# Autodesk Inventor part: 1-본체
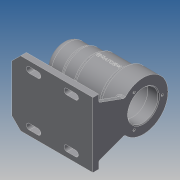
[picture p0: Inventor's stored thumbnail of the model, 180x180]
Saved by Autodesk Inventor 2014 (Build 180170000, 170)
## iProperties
Created: 2017-09
Part Number: 1-본체
Material: Generic
Document SubType Name: Modeling
Designer: kb542-00
Density: 1 g/cm^3
Appearance: Default
Author: kb542-00
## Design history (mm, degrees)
sketch "스케치1"
  geometry: L1 (-112, 0)-(0, 0); L2 (0, 21)-(0, 34); L3 (0, 34)-(-28, 34); L4 (-28, 34)-(-28, 30); L5 (-28, 30)-(-67, 30); L6 (-67, 30)-(-67, 27); L7 (-67, 27)-(-87, 27); L8 (-87, 27)-(-87, 25); L9 (-87, 25)-(-112, 25); L10 (-112, 25)-(-112, 0); L11 (-106, 0)-(-106, 10.5); L12 (-106, 10.5)-(-103, 10.5); L13 (-103, 10.5)-(-103, 16); L14 (-103, 16)-(-99, 16); L15 (-99, 16)-(-99, 17.5); L16 (-99, 17.5)-(-81, 17.5); L17 (-81, 17.5)-(-81, 21); L18 (-81, 21)-(-69, 21); L19 (-69, 21)-(-69, 24); L20 (-69, 24)-(-15, 24); L21 (-15, 24)-(-15, 21); L22 (-15, 21)-(0, 21); 1 further point
  constraints: 44 end point, 15 parallel, 6 perpendicular, 1 coincident, 1 horizontal, 1 point on line, 1 vertical alignment
  dimensions: "d0" = 68 diameter of L3 L1; "d1" = 42 diameter of L22 L1; "d2" = 112 distance between parallel lines of L2 L10; "d3" = 25 distance between parallel lines of L8 L10; "d4" = 45 distance between parallel lines of L6 L10; "d5" = 84 distance between parallel lines of L4 L10; "d6" = 48 diameter of L20 L1; "d7" = 15 distance between parallel lines of L2 L21; "d8" = 42 diameter of L18 L1; "d9" = 3 distance between parallel lines of L13 L11; "d10" = 4 distance between parallel lines of L15 L13; "d11" = 18 distance between parallel lines of L17 L15; "d12" = 12 distance between parallel lines of L19 L17; "d13" = 54 distance between parallel lines of L21 L19; "d14" = 21 diameter of L12 L1; "d15" = 32 diameter of L14 L1; "d16" = 35 diameter of L16 L1; "d17" = 50 diameter of L9 L1; "d18" = 54 diameter of L7 L1; "d19" = 60 diameter of L5 L1
revolve "회전1" sketch "스케치1" stored, may be unused: angle "d20" = 90 deg
fillet "모깎기1" dims "d21" = 9
node "작업 평면1"
sketch "스케치2"
  geometry: L1 (0, 45)-(100, 45); L2 (112, 33)-(112, -33); L3 (100, -45)-(0, -45); L4 (0, -45)-(0, 45); L5 (100, 45)-(112, 33); L6 (112, -33)-(100, -45); L7 (24, 34)-(36, 34); L8 (24, 30)-(36, 30); L9 (36, 38)-(24, 38); L10 (76, 34)-(88, 34); L11 (76, 30)-(88, 30); L12 (88, 38)-(76, 38); L13 (24, -34)-(36, -34); L14 (24, -38)-(36, -38); L15 (36, -30)-(24, -30); L16 (76, -34)-(88, -34); L17 (76, -38)-(88, -38); L18 (88, -30)-(76, -30); A1 r 4 centre (24, 34) between (24, 38) and (24, 30); A2 r 4 centre (36, 34) between (36, 30) and (36, 38); A3 r 4 centre (76, 34) between (76, 38) and (76, 30); A4 r 4 centre (88, 34) between (88, 30) and (88, 38); A5 r 4 centre (24, -34) between (24, -30) and (24, -38); A6 r 4 centre (36, -34) between (36, -38) and (36, -30); A7 r 4 centre (76, -34) between (76, -30) and (76, -38); A8 r 4 centre (88, -34) between (88, -38) and (88, -30); 8 further points
  constraints: 44 end point, 16 point on circle, 16 tangent, 9 parallel, 8 centre point, 5 midpoint, 4 point on line, 2 vertical alignment, 1 coincident, 1 horizontal, 1 perpendicular
  dimensions: "d25" = 90 distance between parallel lines of L3 L1; "d26" = 112 distance between parallel lines of L2 L4; "d27" = 12 distance of L1.end point (112, 45); "d28" = 12 distance of L2.start point (112, 45) (= d27); "d29" = 12 distance of L2.end point (112, -45) (= d27); "d30" = 12 distance of L3.start point (112, -45) (= d29); "d31" = 34 vertical distance of point (0, 0) L7.start; "d32" = 34 vertical distance of point (0, 0) L13.start; "d33" = 4 radius of A1; "d34" = 4 radius of A3; "d35" = 4 radius of A6; "d36" = 4 radius of A8; "d37" = 12 distance of L13.end L13.start; "d38" = 12 distance of L7.end L7.start; "d39" = 12 distance of L10.end L10.start; "d40" = 12 distance of L16.end L16.start; "d41" = 24 distance from line of L7.start L4; "d42" = 24 distance from line of L13.start L4; "d43" = 34 vertical distance of point (0, 0) L16.end; "d44" = 34 vertical distance of point (0, 0) L10.end; "d45" = 40 distance of L7.end L10.start; "d46" = 40 distance of L16.start L13.end
extrude "돌출1" join sketch "스케치2" distance "d47" = 8; taper "d48" = 0 deg
sketch "스케치3"
  geometry: L1 (-103, 25)-(-87, 25) reference; L2 (-87, 25)-(-87, 27) reference; L3 (-87, 27)-(-67, 27) reference; L4 (-67, 27)-(-67, 30) reference; L5 (-67, 30)-(-28, 30) reference; L6 (-28, 30)-(-28, 34) reference; L7 (-28, 34)-(0, 34) reference; L8 (0, 34)-(0, 21) reference; L9 (0, 21)-(-15, 21) reference; L10 (-15, 21)-(-15, 24) reference; L11 (-15, 24)-(-69, 24) reference; L12 (-69, 24)-(-69, 21) reference; L13 (-69, 21)-(-81, 21) reference; L14 (-81, 21)-(-81, 17.5) reference; L15 (-81, 17.5)-(-99, 17.5) reference; L16 (-99, 17.5)-(-99, 16) reference; L17 (-99, 16)-(-103, 16) reference; L18 (-103, 16)-(-103, 10.5) reference; L19 (-103, 10.5)-(-106, 10.5) reference; L20 (-106, 10.5)-(-106, -10.5) reference; L21 (-106, -10.5)-(-103, -10.5) reference; L22 (-103, -10.5)-(-103, -16) reference; L23 (-103, -16)-(-99, -16) reference; L24 (-99, -16)-(-99, -17.5) reference; L25 (-99, -17.5)-(-81, -17.5) reference; L26 (-81, -17.5)-(-81, -21) reference; L27 (-81, -21)-(-69, -21) reference; L28 (-69, -21)-(-69, -24) reference; L29 (-69, -24)-(-15, -24) reference; L30 (-15, -24)-(-15, -21) reference; L31 (-15, -21)-(0, -21) reference; L32 (0, -21)-(0, -34) reference; L33 (0, -34)-(-28, -34) reference; L34 (-28, -34)-(-28, -30) reference; L35 (-28, -30)-(-67, -30) reference; L36 (-67, -30)-(-67, -27) reference; L37 (-67, -27)-(-87, -27) reference; L38 (-87, -27)-(-87, -25) reference; L39 (-87, -25)-(-103, -25) reference; L40 (-112, -16)-(-112, 16) reference; L41 (0, -62)-(0, -70) reference; L42 (0, -70)-(-112, -70) reference; L43 (-112, -70)-(-112, -62) reference; L44 (-112, -62)-(0, -62) reference; L45 (0, -62)-(-100, -62) reference; L46 (-90, -62)-(-80.622, -27); A1 r 9 centre (-103, 16) between (-103, 25) and (-112, 16) reference; A2 r 9 centre (-103, -16) between (-112, -16) and (-103, -25) reference; 1 further point
  constraints: 2 end point, 2 point on line
  dimensions: "d49" = 105 deg angle of L46 L45; "d50" = 22 distance from line of L46.start L43
  node "절단 모서리 투영1"
sketch "스케치7"
  geometry: L1 (-70, 45)-(-62, 45) reference; L2 (-62, 45)-(-62, -45) reference; L3 (-62, -45)-(-70, -45) reference; L4 (-70, -45)-(-70, 45) reference; L5 (-26.008, 21.9)-(-62, 35); L6 (-62, 45)-(-62, -45) reference; L7 (-26.008, -21.9)-(-62, -35); L8 (-62, -35)-(-62, 35); C1 r 21 at (0, 0) reference; C2 r 16 at (0, 0) reference; C3 r 34 at (0, 0); A1 r 34 centre (0, 0) between (-26.008, 21.9) and (-26.008, -21.9) reference; A2 r 34 centre (0, 0) between (-26.008, 21.9) and (-26.008, -21.9) reference; A3 r 34 centre (0, 0) between (-26.008, 21.9) and (-26.008, -21.9); 1 further point
  constraints: 6 end point, 6 point on circle, 2 centre point, 2 coincident, 2 point on line, 1 collinear
  dimensions: "d63" = 110 deg angle of L6 L7; "d64" = 110 deg angle of L2 L5; "d65" = 10 distance from line of L5.end L1; "d66" = 10 distance from line of L3 L7.end
extrude "돌출2" join sketch "스케치7" distance "d68" = 8; taper "d69" = 0 deg
feature "리브1" dims "d70" = 1, "d71" = 8, "d72" = 0, "d73" = 0, "d74" = 1, "d75" = 1
sketch "스케치8" dims "d76" = 52
  geometry: C1 r 21 at (45, 70) reference; A1 r 34 centre (45, 70) between (66.9, 43.992) and (23.1, 43.992) reference; 2 further points
  constraints: 2 vertical alignment, 1 coincident, 2 other
hole "구멍1" sketch "스케치8" at (45, 96) diameter "d77" = 3.242; stored, may be unused: countersink angle "d81" = 90 deg, drill point angle "d83" = 118 deg; dims "d78" = 8, "d79" = 4, "d80" = 2, "d82" = 11
chamfer "모따기1" distance "d87" = 1; stored, may be unused: second distance "d88" = 2, angle "d89" = 45 deg
fillet "모깎기2" dims "d90" = 0.3
fillet "모깎기3" dims "d91" = 3
fillet "모깎기4" dims "d92" = 3
node "작업 평면3"
sketch "스케치9"
  geometry: L1 (47.5, -24.711)-(47.5, 34) reference; 2 further points
  constraints: 1 horizontal alignment, 1 other
  dimensions: "d94" = 48 distance from line of point (-0.5, 0) L1
feature "엠보싱1" sketch "스케치9" dims "d0" = 68, "d1" = 42, "d2" = 112, "d3" = 25, "d4" = 45, "d5" = 84, "d6" = 48, "d7" = 15, "d8" = 42, "d9" = 3, "d10" = 4, "d11" = 18, "d12" = 12, "d13" = 54, "d14" = 21, "d15" = 32, "d16" = 35, "d17" = 50, "d18" = 54, "d19" = 60, "d95" = 0.5, "d96" = 0
node "솔리드1"
pattern_circular "원형 패턴1" dims angle "d85" = 360 deg
node "절단 모서리 투영4"
